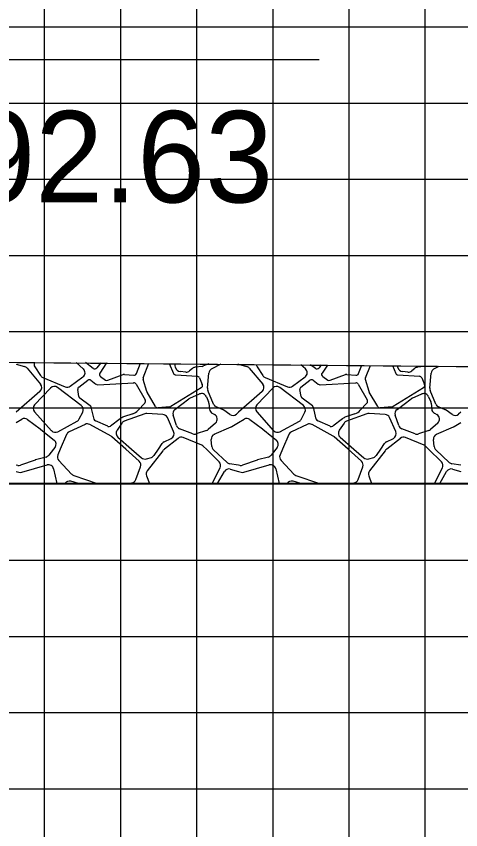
# Model space of a CAD drawing. Extents: x 1807045 to 1807388, y 442591 to 442811.
# Drawn here: x 1807273.39 to 1807279.22, y 442670.13 to 442680.8 of the extents above; entities that cross this region are included whole.
import ezdxf

# ---------------------------------------------------------------- set-up
doc = ezdxf.new("R2010")
doc.units = 0
for name, color, linetype in [('ANNOTATION', 7, 'Continuous'), ('D_Roadway_SlopeLines', 7, 'Continuous'), ('MAJOR', 7, 'Continuous'), ('MINOR', 7, 'Continuous'), ('S_Roadway_Centerline', 7, 'Continuous')]:
    doc.layers.add(name, color=color, linetype=linetype)

msp = doc.modelspace()

# ---------------------------------------------------------------- linework, layer by layer
at = {"layer": 'ANNOTATION'}
msp.add_lwpolyline([(1807277.365, 442680.235), (1807271.674, 442680.235), (1807269.759, 442676.294)], dxfattribs=at)
at = {"layer": 'D_Roadway_SlopeLines'}
for p, q in [((1807274.267, 442676.176), (1807274.175, 442676.259)), ((1807274.396, 442676.182), (1807274.297, 442676.258)), ((1807274.496, 442676.256), (1807274.444, 442676.188)), ((1807274.573, 442676.255), (1807274.484, 442676.122)), ((1807274.964, 442676.114), (1807275.017, 442676.251)), ((1807275.054, 442676.059), (1807275.13, 442676.25)), ((1807275.394, 442676.247), (1807275.452, 442676.116)), ((1807275.48, 442676.195), (1807275.469, 442676.247)), ((1807273.387, 442676.237), (1807273.494, 442676.208)), ((1807273.529, 442676.186), (1807273.706, 442675.975)), ((1807273.631, 442676.204), (1807273.705, 442676.089)), ((1807275.613, 442676.134), (1807275.54, 442676.141)), ((1807275.701, 442676.182), (1807275.664, 442676.15)), ((1807275.828, 442676.209), (1807275.737, 442676.198)), ((1807275.914, 442676.242), (1807275.846, 442676.214)), ((1807275.953, 442676.175), (1807276.076, 442676.241)), ((1807276.298, 442676.239), (1807276.306, 442676.237)), ((1807276.306, 442676.237), (1807276.412, 442676.208)), ((1807276.447, 442676.186), (1807276.624, 442675.975)), ((1807276.55, 442676.204), (1807276.624, 442676.089)), ((1807277.186, 442676.176), (1807277.126, 442676.23)), ((1807277.315, 442676.182), (1807277.253, 442676.229)), ((1807277.393, 442676.228), (1807277.363, 442676.188)), ((1807277.473, 442676.227), (1807277.403, 442676.122)), ((1807277.883, 442676.114), (1807277.925, 442676.223)), ((1807277.973, 442676.059), (1807278.038, 442676.222)), ((1807278.326, 442676.219), (1807278.371, 442676.116)), ((1807278.399, 442676.195), (1807278.394, 442676.218)), ((1807278.531, 442676.134), (1807278.459, 442676.141)), ((1807278.62, 442676.182), (1807278.582, 442676.15)), ((1807278.747, 442676.209), (1807278.656, 442676.198)), ((1807278.766, 442676.215), (1807278.765, 442676.214)), ((1807278.872, 442676.175), (1807278.943, 442676.213)), ((1807273.736, 442676.064), (1807274.029, 442675.939)), ((1807274.097, 442675.947), (1807274.262, 442676.07)), ((1807274.493, 442676.074), (1807274.56, 442676.03)), ((1807274.591, 442676.026), (1807274.793, 442676.102)), ((1807274.808, 442676.104), (1807274.929, 442676.092)), ((1807275.101, 442675.878), (1807275.053, 442676.037)), ((1807275.481, 442676.096), (1807275.763, 442676.08)), ((1807275.793, 442676.059), (1807275.83, 442675.969)), ((1807275.899, 442675.925), (1807275.917, 442676.121)), ((1807276.655, 442676.064), (1807276.948, 442675.939)), ((1807277.015, 442675.947), (1807277.181, 442676.07)), ((1807277.412, 442676.074), (1807277.479, 442676.03)), ((1807277.51, 442676.026), (1807277.712, 442676.102)), ((1807277.727, 442676.104), (1807277.848, 442676.092)), ((1807278.02, 442675.878), (1807277.972, 442676.037)), ((1807278.4, 442676.096), (1807278.682, 442676.08)), ((1807278.712, 442676.059), (1807278.749, 442675.969)), ((1807278.818, 442675.925), (1807278.836, 442676.121)), ((1807274.239, 442675.694), (1807273.928, 442675.931)), ((1807274.208, 442675.936), (1807274.325, 442676.026)), ((1807274.367, 442676.026), (1807274.434, 442675.975)), ((1807274.457, 442675.968), (1807274.929, 442675.992)), ((1807274.96, 442675.975), (1807275.078, 442675.768)), ((1807275.816, 442675.927), (1807275.418, 442675.682)), ((1807277.158, 442675.694), (1807276.847, 442675.931)), ((1807277.126, 442675.936), (1807277.244, 442676.026)), ((1807277.286, 442676.026), (1807277.353, 442675.975)), ((1807277.376, 442675.968), (1807277.847, 442675.992)), ((1807277.879, 442675.975), (1807277.997, 442675.768)), ((1807278.735, 442675.927), (1807278.337, 442675.682)), ((1807273.698, 442675.879), (1807273.387, 442675.606)), ((1807273.837, 442675.924), (1807273.628, 442675.705)), ((1807274.208, 442675.815), (1807274.195, 442675.904)), ((1807275.216, 442675.681), (1807275.104, 442675.871)), ((1807275.668, 442675.791), (1807275.793, 442675.847)), ((1807275.978, 442675.715), (1807275.904, 442675.893)), ((1807276.617, 442675.879), (1807276.306, 442675.606)), ((1807276.756, 442675.924), (1807276.547, 442675.705)), ((1807277.127, 442675.815), (1807277.113, 442675.904)), ((1807278.135, 442675.681), (1807278.023, 442675.871)), ((1807278.586, 442675.791), (1807278.712, 442675.847)), ((1807278.897, 442675.715), (1807278.823, 442675.893)), ((1807274.357, 442675.693), (1807274.222, 442675.792)), ((1807275.074, 442675.728), (1807274.986, 442675.632)), ((1807275.47, 442675.644), (1807275.654, 442675.783)), ((1807275.884, 442675.811), (1807275.912, 442675.745)), ((1807275.918, 442675.724), (1807275.925, 442675.647)), ((1807277.276, 442675.693), (1807277.14, 442675.792)), ((1807277.993, 442675.728), (1807277.905, 442675.632)), ((1807278.388, 442675.644), (1807278.573, 442675.783)), ((1807278.802, 442675.811), (1807278.831, 442675.745)), ((1807278.836, 442675.724), (1807278.843, 442675.647)), ((1807273.627, 442675.612), (1807273.848, 442675.365)), ((1807274.214, 442675.52), (1807274.259, 442675.609)), ((1807274.408, 442675.517), (1807274.37, 442675.674)), ((1807275.403, 442675.677), (1807275.248, 442675.665)), ((1807276.103, 442675.639), (1807276.014, 442675.678)), ((1807276.193, 442675.577), (1807276.115, 442675.633)), ((1807276.306, 442675.606), (1807276.278, 442675.582)), ((1807276.546, 442675.612), (1807276.767, 442675.365)), ((1807277.133, 442675.52), (1807277.177, 442675.609)), ((1807277.327, 442675.517), (1807277.289, 442675.674)), ((1807278.322, 442675.677), (1807278.167, 442675.665)), ((1807279.021, 442675.639), (1807278.932, 442675.678)), ((1807279.112, 442675.577), (1807279.033, 442675.633)), ((1807279.224, 442675.606), (1807279.196, 442675.582)), ((1807273.387, 442675.472), (1807273.461, 442675.515)), ((1807273.536, 442675.511), (1807273.702, 442675.388)), ((1807274.751, 442675.521), (1807274.624, 442675.426)), ((1807274.917, 442675.587), (1807274.797, 442675.545)), ((1807275.074, 442675.587), (1807274.806, 442675.489)), ((1807275.313, 442675.579), (1807275.101, 442675.591)), ((1807275.453, 442675.353), (1807275.372, 442675.538)), ((1807275.492, 442675.433), (1807275.446, 442675.567)), ((1807275.961, 442675.593), (1807275.991, 442675.577)), ((1807276.306, 442675.472), (1807276.379, 442675.515)), ((1807276.455, 442675.511), (1807276.621, 442675.388)), ((1807277.67, 442675.521), (1807277.543, 442675.426)), ((1807277.835, 442675.587), (1807277.716, 442675.545)), ((1807277.993, 442675.587), (1807277.725, 442675.489)), ((1807278.232, 442675.579), (1807278.02, 442675.591)), ((1807278.372, 442675.353), (1807278.29, 442675.538)), ((1807278.41, 442675.433), (1807278.365, 442675.567)), ((1807278.88, 442675.593), (1807278.91, 442675.577)), ((1807273.932, 442675.351), (1807274.186, 442675.49)), ((1807274.29, 442675.448), (1807274.081, 442675.349)), ((1807274.632, 442675.293), (1807274.352, 442675.446)), ((1807274.59, 442675.422), (1807274.427, 442675.494)), ((1807274.773, 442675.463), (1807274.71, 442675.37)), ((1807275.705, 442675.324), (1807275.532, 442675.391)), ((1807276.004, 442675.465), (1807275.908, 442675.381)), ((1807275.988, 442675.317), (1807276.211, 442675.416)), ((1807276.218, 442675.42), (1807276.306, 442675.472)), ((1807276.85, 442675.351), (1807277.105, 442675.49)), ((1807277.209, 442675.448), (1807277, 442675.349)), ((1807277.55, 442675.293), (1807277.271, 442675.446)), ((1807277.509, 442675.422), (1807277.346, 442675.494)), ((1807277.692, 442675.463), (1807277.629, 442675.37)), ((1807278.624, 442675.324), (1807278.451, 442675.391)), ((1807278.923, 442675.465), (1807278.827, 442675.381)), ((1807278.907, 442675.317), (1807279.13, 442675.416)), ((1807279.137, 442675.42), (1807279.224, 442675.472)), ((1807273.704, 442675.386), (1807273.824, 442675.289)), ((1807273.824, 442675.289), (1807273.884, 442675.241)), ((1807274.048, 442675.314), (1807273.965, 442675.122)), ((1807275.885, 442675.368), (1807275.751, 442675.323)), ((1807276.623, 442675.386), (1807276.742, 442675.289)), ((1807276.743, 442675.289), (1807276.803, 442675.241)), ((1807276.966, 442675.314), (1807276.884, 442675.122)), ((1807278.804, 442675.368), (1807278.67, 442675.323)), ((1807274.825, 442675.122), (1807274.644, 442675.284)), ((1807274.722, 442675.28), (1807274.902, 442675.122)), ((1807275.254, 442675.122), (1807275.303, 442675.195)), ((1807275.329, 442675.218), (1807275.421, 442675.264)), ((1807275.512, 442675.264), (1807275.335, 442675.122)), ((1807275.825, 442675.174), (1807275.581, 442675.274)), ((1807275.956, 442675.157), (1807275.948, 442675.248)), ((1807277.744, 442675.122), (1807277.563, 442675.284)), ((1807277.64, 442675.28), (1807277.821, 442675.122)), ((1807278.173, 442675.122), (1807278.222, 442675.195)), ((1807278.248, 442675.218), (1807278.34, 442675.264)), ((1807278.431, 442675.264), (1807278.254, 442675.122)), ((1807278.744, 442675.174), (1807278.499, 442675.274)), ((1807278.875, 442675.157), (1807278.866, 442675.248)), ((1807273.877, 442675.122), (1807273.815, 442675.043)), ((1807273.895, 442675.145), (1807273.877, 442675.122)), ((1807273.965, 442675.122), (1807273.933, 442675.047)), ((1807275.001, 442674.965), (1807274.825, 442675.122)), ((1807274.902, 442675.122), (1807275.032, 442675.008)), ((1807275.312, 442675.102), (1807275.107, 442674.836)), ((1807275.199, 442675.041), (1807275.254, 442675.122)), ((1807275.335, 442675.122), (1807275.323, 442675.113)), ((1807275.884, 442675.122), (1807275.847, 442675.159)), ((1807276.051, 442674.954), (1807275.884, 442675.122)), ((1807276.155, 442674.948), (1807275.977, 442675.113)), ((1807276.796, 442675.122), (1807276.734, 442675.043)), ((1807276.814, 442675.145), (1807276.796, 442675.122)), ((1807276.884, 442675.122), (1807276.851, 442675.047)), ((1807277.92, 442674.965), (1807277.744, 442675.122)), ((1807277.821, 442675.122), (1807277.951, 442675.008)), ((1807278.231, 442675.102), (1807278.026, 442674.836)), ((1807278.117, 442675.041), (1807278.173, 442675.122)), ((1807278.254, 442675.122), (1807278.242, 442675.113)), ((1807278.802, 442675.122), (1807278.766, 442675.159)), ((1807278.97, 442674.954), (1807278.802, 442675.122)), ((1807279.073, 442674.948), (1807278.896, 442675.113)), ((1807273.633, 442674.979), (1807273.441, 442674.91)), ((1807273.779, 442675.019), (1807273.638, 442674.98)), ((1807273.946, 442674.973), (1807274.114, 442674.796)), ((1807275.097, 442674.995), (1807275.162, 442675.014)), ((1807276.552, 442674.979), (1807276.36, 442674.91)), ((1807276.698, 442675.019), (1807276.557, 442674.98)), ((1807276.864, 442674.973), (1807277.033, 442674.796)), ((1807278.016, 442674.995), (1807278.081, 442675.014)), ((1807273.406, 442674.907), (1807273.387, 442674.911)), ((1807273.458, 442674.819), (1807273.792, 442674.915)), ((1807273.877, 442674.863), (1807273.919, 442674.671)), ((1807274.959, 442674.723), (1807275.02, 442674.891)), ((1807275.96, 442674.671), (1807276.064, 442674.875)), ((1807276.306, 442674.911), (1807276.189, 442674.931)), ((1807276.198, 442674.859), (1807276.306, 442674.829)), ((1807276.325, 442674.907), (1807276.306, 442674.911)), ((1807276.377, 442674.819), (1807276.71, 442674.915)), ((1807276.796, 442674.863), (1807276.838, 442674.671)), ((1807277.877, 442674.723), (1807277.938, 442674.891)), ((1807278.879, 442674.671), (1807278.983, 442674.875)), ((1807279.224, 442674.911), (1807279.108, 442674.931)), ((1807279.117, 442674.859), (1807279.224, 442674.829)), ((1807273.387, 442674.829), (1807273.42, 442674.819)), ((1807274.141, 442674.778), (1807274.45, 442674.671)), ((1807275.097, 442674.77), (1807275.135, 442674.671)), ((1807276.029, 442674.671), (1807276.12, 442674.828)), ((1807276.306, 442674.829), (1807276.339, 442674.819)), ((1807277.06, 442674.778), (1807277.369, 442674.671)), ((1807278.016, 442674.77), (1807278.054, 442674.671)), ((1807278.948, 442674.671), (1807279.039, 442674.828)), ((1807274.204, 442674.671), (1807274.103, 442674.701)), ((1807274.84, 442674.671), (1807274.902, 442674.678)), ((1807277.123, 442674.671), (1807277.022, 442674.701)), ((1807277.759, 442674.671), (1807277.821, 442674.678))]:
    msp.add_line(p, q, dxfattribs=at)
msp.add_lwpolyline([(1807266.734, 442676.331), (1807269.759, 442676.294), (1807283.258, 442676.171), (1807283.258, 442674.671), (1807267.054, 442674.671)], dxfattribs=at)
for centre, major_axis, start_param, end_param in [((1807273.688, 442676.241), (0, 0.0683), 1.228521, 2.146101), ((1807273.476, 442676.142), (0, 0.0683), 5.40978, 6.025862), ((1807274.222, 442676.125), (0, -0.0683), 0.638914, 2.406418), ((1807274.417, 442676.209), (0, -0.0342), 5.630339, 7.201135), ((1807275.547, 442676.209), (0, -0.0683), 4.928939, 6.183517), ((1807275.619, 442676.202), (0, -0.0683), 6.183517, 6.987679), ((1807275.746, 442676.13), (0, 0.0683), 0.124355, 0.704494), ((1807275.82, 442676.277), (0, -0.0683), 0.124355, 0.394791), ((1807275.985, 442676.115), (0, 0.0683), 0.489957, 1.480136), ((1807276.395, 442676.142), (0, 0.0683), 5.40978, 6.025862), ((1807276.607, 442676.241), (0, 0.0683), 1.648488, 2.146101), ((1807277.14, 442676.125), (0, -0.0683), 0.638914, 2.406418), ((1807277.336, 442676.209), (0, -0.0342), 5.630339, 7.201135), ((1807278.465, 442676.209), (0, -0.0683), 4.928939, 6.183517), ((1807278.538, 442676.202), (0, -0.0683), 6.183517, 6.987679), ((1807278.664, 442676.13), (0, 0.0683), 0.124355, 0.704494), ((1807278.739, 442676.277), (0, -0.0683), 0.124355, 0.394791), ((1807278.904, 442676.115), (0, 0.0683), 0.489957, 1.480136), ((1807273.763, 442676.126), (0, -0.0683), 5.287694, 5.881372), ((1807274.346, 442675.999), (0, 0.0342), 5.62749, 6.938291), ((1807274.512, 442676.103), (0, 0.0342), 0.982794, 2.55359), ((1807274.805, 442676.07), (0, 0.0342), 6.185932, 6.640689), ((1807274.933, 442676.126), (0, -0.0342), 6.185932, 7.487587), ((1807275.086, 442676.047), (0, -0.0342), 4.331883, 5.00783), ((1807275.483, 442676.13), (0, -0.0342), 5.126896, 6.225111), ((1807275.761, 442676.045), (0, 0.0342), 5.10718, 6.225111), ((1807276.681, 442676.126), (0, -0.0683), 5.287694, 5.881372), ((1807277.265, 442675.999), (0, 0.0342), 5.62749, 6.938291), ((1807277.431, 442676.103), (0, 0.0342), 0.982794, 2.55359), ((1807277.724, 442676.07), (0, 0.0342), 6.185932, 6.640689), ((1807277.851, 442676.126), (0, -0.0342), 6.185932, 7.487587), ((1807278.004, 442676.047), (0, -0.0342), 4.331883, 5.00783), ((1807278.402, 442676.13), (0, -0.0342), 5.126896, 6.225111), ((1807278.68, 442676.045), (0, 0.0342), 5.10718, 6.225111), ((1807273.653, 442675.931), (0, 0.0683), 3.861663, 5.40978), ((1807273.886, 442675.877), (0, 0.0683), 5.631073, 7.093578), ((1807274.056, 442676.002), (0, -0.0683), 5.881372, 6.922099), ((1807274.228, 442675.909), (0, -0.0342), 3.796699, 4.865038), ((1807274.455, 442676.002), (0, -0.0342), 5.62749, 6.335377), ((1807274.579, 442676.058), (0, -0.0342), 5.695183, 6.640689), ((1807274.93, 442675.958), (0, 0.0342), 5.232357, 6.335377), ((1807275.799, 442675.956), (0, 0.0342), 3.692268, 5.10718), ((1807275.967, 442675.919), (0, -0.0683), 4.621729, 5.104729), ((1807276.572, 442675.931), (0, 0.0683), 3.861663, 5.40978), ((1807276.805, 442675.877), (0, 0.0683), 5.631073, 7.093578), ((1807276.975, 442676.002), (0, -0.0683), 5.881372, 6.922099), ((1807277.147, 442675.909), (0, -0.0342), 3.796699, 4.865038), ((1807277.374, 442676.002), (0, -0.0342), 5.62749, 6.335377), ((1807277.498, 442676.058), (0, -0.0342), 5.695183, 6.640689), ((1807277.849, 442675.958), (0, 0.0342), 5.232357, 6.335377), ((1807278.717, 442675.956), (0, 0.0342), 3.692268, 5.10718), ((1807278.886, 442675.919), (0, -0.0683), 4.621729, 5.104729), ((1807275.134, 442675.888), (0, -0.0342), 5.00783, 5.244893), ((1807275.821, 442675.784), (0, 0.0683), 5.120538, 6.699624), ((1807278.052, 442675.888), (0, -0.0342), 5.00783, 5.244893), ((1807278.74, 442675.784), (0, 0.0683), 5.120538, 6.699624), ((1807274.242, 442675.82), (0, -0.0342), 4.865038, 5.649393), ((1807275.049, 442675.751), (0, 0.0342), 3.967509, 5.232357), ((1807275.695, 442675.728), (0, 0.0683), 0.416439, 0.646119), ((1807275.85, 442675.718), (0, 0.0683), 4.803049, 5.120538), ((1807276.041, 442675.741), (0, -0.0683), 5.104729, 5.870775), ((1807277.161, 442675.82), (0, -0.0342), 4.865038, 5.649393), ((1807277.968, 442675.751), (0, 0.0342), 3.967509, 5.232357), ((1807278.614, 442675.728), (0, 0.0683), 0.416439, 0.646119), ((1807278.768, 442675.718), (0, 0.0683), 4.803049, 5.120538), ((1807278.96, 442675.741), (0, -0.0683), 5.104729, 5.870775), ((1807273.678, 442675.658), (0, 0.0683), 0.810393, 2.300927), ((1807274.198, 442675.639), (0, -0.0683), 1.108164, 2.48948), ((1807274.337, 442675.666), (0, 0.0342), 4.95256, 5.649393), ((1807274.861, 442675.748), (0, -0.171), 0.333945, 0.825917), ((1807275.245, 442675.699), (0, -0.0342), 5.244893, 6.364637), ((1807275.401, 442675.712), (0, -0.0342), 0.081452, 0.550676), ((1807275.511, 442675.589), (0, -0.0683), 3.787712, 5.039487), ((1807275.993, 442675.653), (0, -0.0683), 4.803049, 5.799738), ((1807276.075, 442675.577), (0, 0.0683), 5.668522, 5.870775), ((1807276.597, 442675.658), (0, 0.0683), 0.810393, 2.300927), ((1807277.116, 442675.639), (0, -0.0683), 1.108164, 2.48948), ((1807277.255, 442675.666), (0, 0.0342), 4.95256, 5.649393), ((1807277.779, 442675.748), (0, -0.171), 0.333945, 0.825917), ((1807278.164, 442675.699), (0, -0.0342), 5.244893, 6.364637), ((1807278.319, 442675.712), (0, -0.0342), 0.081452, 0.550676), ((1807278.429, 442675.589), (0, -0.0683), 3.787712, 5.039487), ((1807278.911, 442675.653), (0, -0.0683), 4.803049, 5.799738), ((1807278.994, 442675.577), (0, 0.0683), 5.668522, 5.870775), ((1807273.495, 442675.457), (0, 0.0683), 5.645637, 6.81814), ((1807274.153, 442675.55), (0, -0.0683), 0.501913, 1.108164), ((1807274.441, 442675.525), (0, -0.0342), 4.95256, 5.866747), ((1807274.853, 442675.384), (0, 0.171), 0.333945, 0.641659), ((1807275.097, 442675.522), (0, 0.0683), 6.226907, 6.630952), ((1807275.309, 442675.51), (0, 0.0683), 5.126896, 6.226907), ((1807275.959, 442675.517), (0, 0.0683), 3.860423, 5.799738), ((1807276.233, 442675.633), (0, -0.0683), 5.668522, 7.003256), ((1807276.414, 442675.457), (0, 0.0683), 5.645637, 6.81814), ((1807277.072, 442675.55), (0, -0.0683), 0.501913, 1.108164), ((1807277.36, 442675.525), (0, -0.0342), 4.95256, 5.866747), ((1807277.772, 442675.384), (0, 0.171), 0.333945, 0.641659), ((1807278.016, 442675.522), (0, 0.0683), 6.226907, 6.630952), ((1807278.228, 442675.51), (0, 0.0683), 5.126896, 6.226907), ((1807278.878, 442675.517), (0, 0.0683), 3.860423, 5.799738), ((1807279.151, 442675.633), (0, -0.0683), 5.668522, 7.003256), ((1807274.319, 442675.386), (0, 0.0683), 5.782172, 6.726567), ((1807274.604, 442675.453), (0, -0.0342), 5.866747, 6.924845), ((1807274.83, 442675.425), (0, 0.0683), 0.347767, 0.977446), ((1807275.556, 442675.455), (0, -0.0683), 5.039487, 5.917129), ((1807276.183, 442675.478), (0, -0.0683), 0.418224, 0.534955), ((1807277.238, 442675.386), (0, 0.0683), 5.782172, 6.726567), ((1807277.523, 442675.453), (0, -0.0342), 5.866747, 6.924845), ((1807277.748, 442675.425), (0, 0.0683), 0.347767, 0.977446), ((1807278.475, 442675.455), (0, -0.0683), 5.039487, 5.917129), ((1807279.102, 442675.478), (0, -0.0683), 0.418224, 0.534955), ((1807273.661, 442675.333), (0, 0.0683), 5.600869, 5.645637), ((1807273.867, 442675.343), (0, -0.0683), 5.600869, 5.608444), ((1807273.899, 442675.411), (0, -0.0683), 5.44252, 6.785098), ((1807274.11, 442675.287), (0, 0.0683), 0.443382, 1.163165), ((1807274.599, 442675.233), (0, 0.0683), 5.554357, 5.782172), ((1807274.766, 442675.331), (0, 0.0683), 0.977446, 2.424153), ((1807275.391, 442675.325), (0, -0.0683), 0.463648, 1.985303), ((1807275.73, 442675.388), (0, -0.0683), 5.917129, 6.604936), ((1807275.863, 442675.433), (0, -0.0683), 0.321751, 0.71883), ((1807276.016, 442675.254), (0, -0.0683), 3.559817, 4.803049), ((1807276.58, 442675.333), (0, 0.0683), 5.600869, 5.645637), ((1807276.785, 442675.343), (0, -0.0683), 5.600869, 5.608444), ((1807276.818, 442675.411), (0, -0.0683), 5.44252, 6.785098), ((1807277.029, 442675.287), (0, 0.0683), 0.443382, 1.163165), ((1807277.517, 442675.233), (0, 0.0683), 5.554357, 5.782172), ((1807277.685, 442675.331), (0, 0.0683), 0.977446, 2.424153), ((1807278.309, 442675.325), (0, -0.0683), 0.463648, 1.985303), ((1807278.649, 442675.388), (0, -0.0683), 5.917129, 6.604936), ((1807278.782, 442675.433), (0, -0.0683), 0.321751, 0.71883), ((1807278.934, 442675.254), (0, -0.0683), 3.559817, 4.803049), ((1807273.842, 442675.188), (0, 0.0683), 4.048343, 5.608444), ((1807275.36, 442675.157), (0, 0.0683), 0.463648, 0.97362), ((1807275.555, 442675.211), (0, 0.0683), 5.893869, 6.957926), ((1807276.76, 442675.188), (0, 0.0683), 4.048343, 5.608444), ((1807278.279, 442675.157), (0, 0.0683), 0.463648, 0.97362), ((1807278.473, 442675.211), (0, 0.0683), 5.893869, 6.957926), ((1807275.366, 442675.06), (0, 0.0683), 0.674741, 0.911486), ((1807275.799, 442675.111), (0, 0.0683), 5.497787, 5.893869), ((1807276.024, 442675.163), (0, -0.0683), 4.803049, 5.35086), ((1807276.024, 442675.163), (0, -0.0683), 5.35086, 5.534807), ((1807278.285, 442675.06), (0, 0.0683), 0.674741, 0.911486), ((1807278.718, 442675.111), (0, 0.0683), 5.497787, 5.893869), ((1807278.943, 442675.163), (0, -0.0683), 4.803049, 5.35086), ((1807278.943, 442675.163), (0, -0.0683), 5.35086, 5.534807), ((1807273.656, 442674.915), (0, 0.0683), 0.266252, 0.343024), ((1807273.761, 442675.085), (0, -0.0683), 0.266252, 0.90675), ((1807273.995, 442675.02), (0, 0.0683), 1.163165, 2.331293), ((1807274.955, 442674.914), (0, -0.0683), 1.223118, 2.412764), ((1807275.077, 442675.06), (0, -0.0683), 5.565745, 6.57742), ((1807275.142, 442675.08), (0, -0.0683), 0.294235, 0.97362), ((1807276.575, 442674.915), (0, 0.0683), 0.266252, 0.343024), ((1807276.68, 442675.085), (0, -0.0683), 0.266252, 0.90675), ((1807276.914, 442675.02), (0, 0.0683), 1.163165, 2.331293), ((1807277.874, 442674.914), (0, -0.0683), 1.223118, 2.412764), ((1807277.996, 442675.06), (0, -0.0683), 5.565745, 6.57742), ((1807278.061, 442675.08), (0, -0.0683), 0.294235, 0.97362), ((1807273.418, 442674.975), (0, -0.0683), 6.110995, 6.626209), ((1807273.811, 442674.849), (0, 0.0683), 4.928939, 6.561485), ((1807276.003, 442674.906), (0, -0.0683), 1.099019, 2.356194), ((1807276.179, 442674.794), (0, 0.0683), 6.004886, 7.327354), ((1807276.201, 442674.998), (0, -0.0683), 5.534807, 6.110994), ((1807276.337, 442674.975), (0, -0.0683), 6.110994, 6.626209), ((1807276.729, 442674.849), (0, 0.0683), 4.928939, 6.561485), ((1807278.922, 442674.906), (0, -0.0683), 1.099019, 2.356194), ((1807279.098, 442674.794), (0, 0.0683), 6.004886, 7.327354), ((1807279.12, 442674.998), (0, -0.0683), 5.534807, 6.110994), ((1807273.439, 442674.885), (0, -0.0683), 6.004886, 6.561485), ((1807274.164, 442674.843), (0, -0.0683), 5.472885, 5.950458), ((1807275.161, 442674.795), (0, 0.0683), 0.911486, 1.935998), ((1807276.358, 442674.885), (0, -0.0683), 6.004886, 6.561485), ((1807277.082, 442674.843), (0, -0.0683), 5.472885, 5.950458), ((1807278.08, 442674.795), (0, 0.0683), 0.911486, 1.935998), ((1807274.084, 442674.636), (0, 0.0683), 5.991139, 7.313202), ((1807274.894, 442674.746), (0, -0.0683), 0.113874, 1.223118), ((1807277.002, 442674.636), (0, 0.0683), 5.991139, 7.313202), ((1807277.813, 442674.746), (0, -0.0683), 0.113874, 1.223118)]:
    msp.add_ellipse(centre, major_axis=major_axis, ratio=0.99895, start_param=start_param, end_param=end_param, dxfattribs=at)
at = {"layer": 'MAJOR'}
for p, q in [((1807070.759, 442678.665), (1807350.759, 442678.665)), ((1807070.759, 442673.665), (1807350.759, 442673.665))]:
    msp.add_line(p, q, dxfattribs=at)
at = {"layer": 'MINOR'}
for p, q in [((1807273.759, 442663.665), (1807273.759, 442698.665)), ((1807274.759, 442663.665), (1807274.759, 442698.665)), ((1807275.759, 442663.665), (1807275.759, 442698.665)), ((1807276.759, 442663.665), (1807276.759, 442698.665)), ((1807277.759, 442663.665), (1807277.759, 442698.665)), ((1807278.759, 442663.665), (1807278.759, 442698.665)), ((1807070.759, 442680.665), (1807350.759, 442680.665)), ((1807070.759, 442679.665), (1807350.759, 442679.665)), ((1807070.759, 442677.665), (1807350.759, 442677.665)), ((1807070.759, 442676.665), (1807350.759, 442676.665)), ((1807070.759, 442675.665), (1807350.759, 442675.665)), ((1807070.759, 442674.665), (1807350.759, 442674.665)), ((1807070.759, 442672.665), (1807350.759, 442672.665)), ((1807070.759, 442671.665), (1807350.759, 442671.665)), ((1807070.759, 442670.665), (1807350.759, 442670.665))]:
    msp.add_line(p, q, dxfattribs=at)
at = {"layer": 'S_Roadway_Centerline'}
msp.add_lwpolyline([(1807259.938, 442676.383), (1807289.258, 442676.117), (1807292.175, 442676.101), (1807293.147, 442676.082), (1807293.932, 442676.046), (1807303.798, 442675.634), (1807316.087, 442675.089), (1807317.483, 442675.029), (1807339.15, 442673.287), (1807345.472, 442673.075), (1807349.323, 442673.138), (1807350.759, 442673.094)], dxfattribs=at)

# ---------------------------------------------------------------- texts
at = {"layer": 'ANNOTATION'}
msp.add_text('192.63', height=1.2, dxfattribs=at).set_placement((1807271.852, 442678.361))

doc.saveas('drawing.dxf')
